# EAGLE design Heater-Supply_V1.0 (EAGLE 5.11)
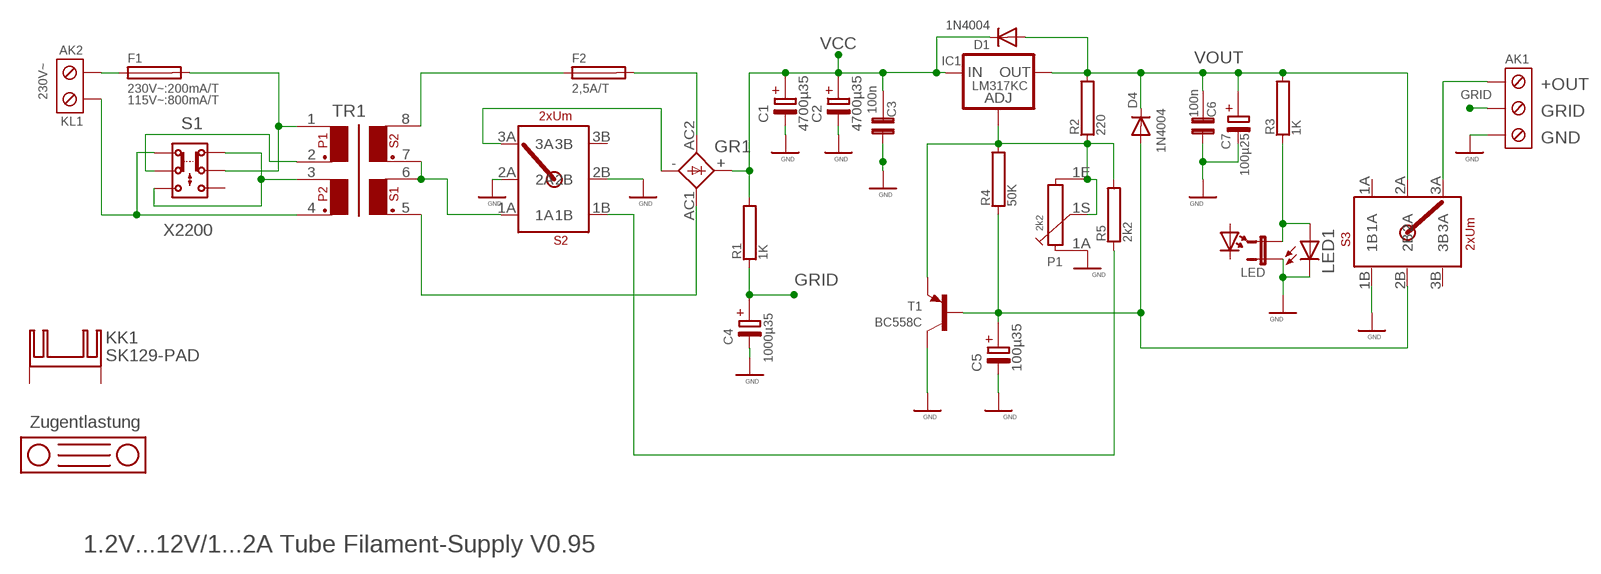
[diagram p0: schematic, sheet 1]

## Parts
AK1  KLEMME3STANDART  [KLEMME3]
AK2  KL1  KLEMME2RM5  [KLEMME2]
C1  4700µ35  E7,5-18  [E7,5-18]
C2  4700µ35  E7,5-18  [E7,5-18]
C3  100n  C2,5/55/2  [C2,5/5-2]
C4  1000µ35  E5-13  [E5-13]
C5  100µ35  E3,5-8  [E3,5-8]
C6  100n  C2,5/55/2  [C2,5/5-2]
C7  100µ25  E2,5-7  [E2,5-7]
D1  1N4004  [DO41-10]
D4  1N4004  [DO41-10]
F1  230V~:200mA/T  SH22,5A  [SH22,5A]
F2  2,5A/T  SH22,5A  [SH22,5A]
GR1  FBU4  [FBU4]
IC1  LM317KC  LM317TS  [317TS]
KK1  SK129-PAD  [SK129]
LED  JP1E  [JP1]
LED1  LED3MM  [LED3MM]
P1  2k2  PC16-SHM2  [PC16-SHM2]
R1  1K  0207/10RD  [0207/10]
R2  220  0207/10RD  [0207/10]
R3  1K  0207/10RD  [0207/10]
R4  50K  0207/10RD  [0207/10]
R5  2k2  0207/10RD  [0207/10]
S1  X2200  [X2200]
S2  2xUm  S-2PRINT  [S-2PRINT]
S3  2xUm  S-2PRINT  [S-2PRINT]
T1  BC558C  BC558C-PNP-TO92-EBC  [TO92-EBC]
TR1  FL24/12  [FL12-24]
U$2  KAZU0442  [KAZU0442]

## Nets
GND: AK1.1 C1.- C2.- C3.2 C3.3 C4.- C5.- C6.2 C6.3 C7.- LED1.K(C) LED.1 P1.1A S2.2A S2.2B S3.1B T1.C
GRID: AK1.2 C4.+ R1.1
N$1: F2.1 TR1.8
N$2: AK1.3 S3.3A
N$3: S2.1A TR1.6 TR1.7
N$4: AK2.1 F1.1
N$5: F1.2 S1.1.2 TR1.1
N$6: S1.2.2 TR1.2
N$7: GR1.- S2.3A
N$9: C5.+ D4.A R4.1 S3.2B T1.B
N$10: R5.1 S2.1B
N$13: LED1.A LED.2 R3.1
N$15: IC1.1(ADJ) P1.1E P1.1S R2.1 R4.2 R5.2 T1.E
N$18: AK2.2 S1.2.1 TR1.4
N$20: GR1.AC1(AC2) TR1.5
N$21: F2.2 GR1.AC2(AC1)
N$24: S1.1.1 S1.2.3 TR1.3
VCC: C1.+ C2.+ C3.1 D1.C GR1.+ IC1.3(IN) R1.2
VOUT: C6.1 C7.+ D1.A D4.C IC1.2(OUT) R2.2 R3.2 S3.2A
Unconnected: KK1.A2,5(K) KK1.B2,5(K) P1.M1 P1.M2 P1.M3 P1.M4 S1.1.3 S2.3B S3.1A S3.3B

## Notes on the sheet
- +OUT
- 230V~
- 115V~:800mA/T
- GRID
- GND
- Zugentlastung
- 1.2V...12V/1...2A Tube Filament-Supply V0.95

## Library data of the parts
AK1 = VERBINDE:KLEMME3
AK2 = VERBINDE:KLEMME2
C1 C2 = Elkos:E7,5-18
C3 C6 = CAP-Kondensatoren:C2,5/5
C4 = Elkos:E5-13
C5 = Elkos:E3,5-8
C7 = Elkos:E2,5-7
D1 D4 = diode:1N4004: DIODE
F1 F2 = fuse:SH22,5A: FUSE HOLDER; MPN: 0031.7701.11; OC_FARNELL: unknown; OC_NEWARK: 04F1224
GR1 = Gleichrichter:FBU4: FAGOR RECTIFIER grid 3 x 5 mm
IC1 = v-reg:LM317TS: VOLTAGE REGULATOR
KK1 = heatsink:SK129-PAD: HEATSINK
LED = jumper:JP1E: JUMPER
LED1 = led:LED: LED
P1 = Potentiometer-piher:PC16-SHM2: POTENTIOMETER single carbon potentiometer, 16 mm, S3ROH
R1-R5 = R:0207/10
S1 = switch:X2200
S2 S3 = Schalter:S-2PRINT
T1 = transistor:*-PNP-: PNP Transistror
TR1 = trafo:FL24/12
U$2 = MB:KAZU0442

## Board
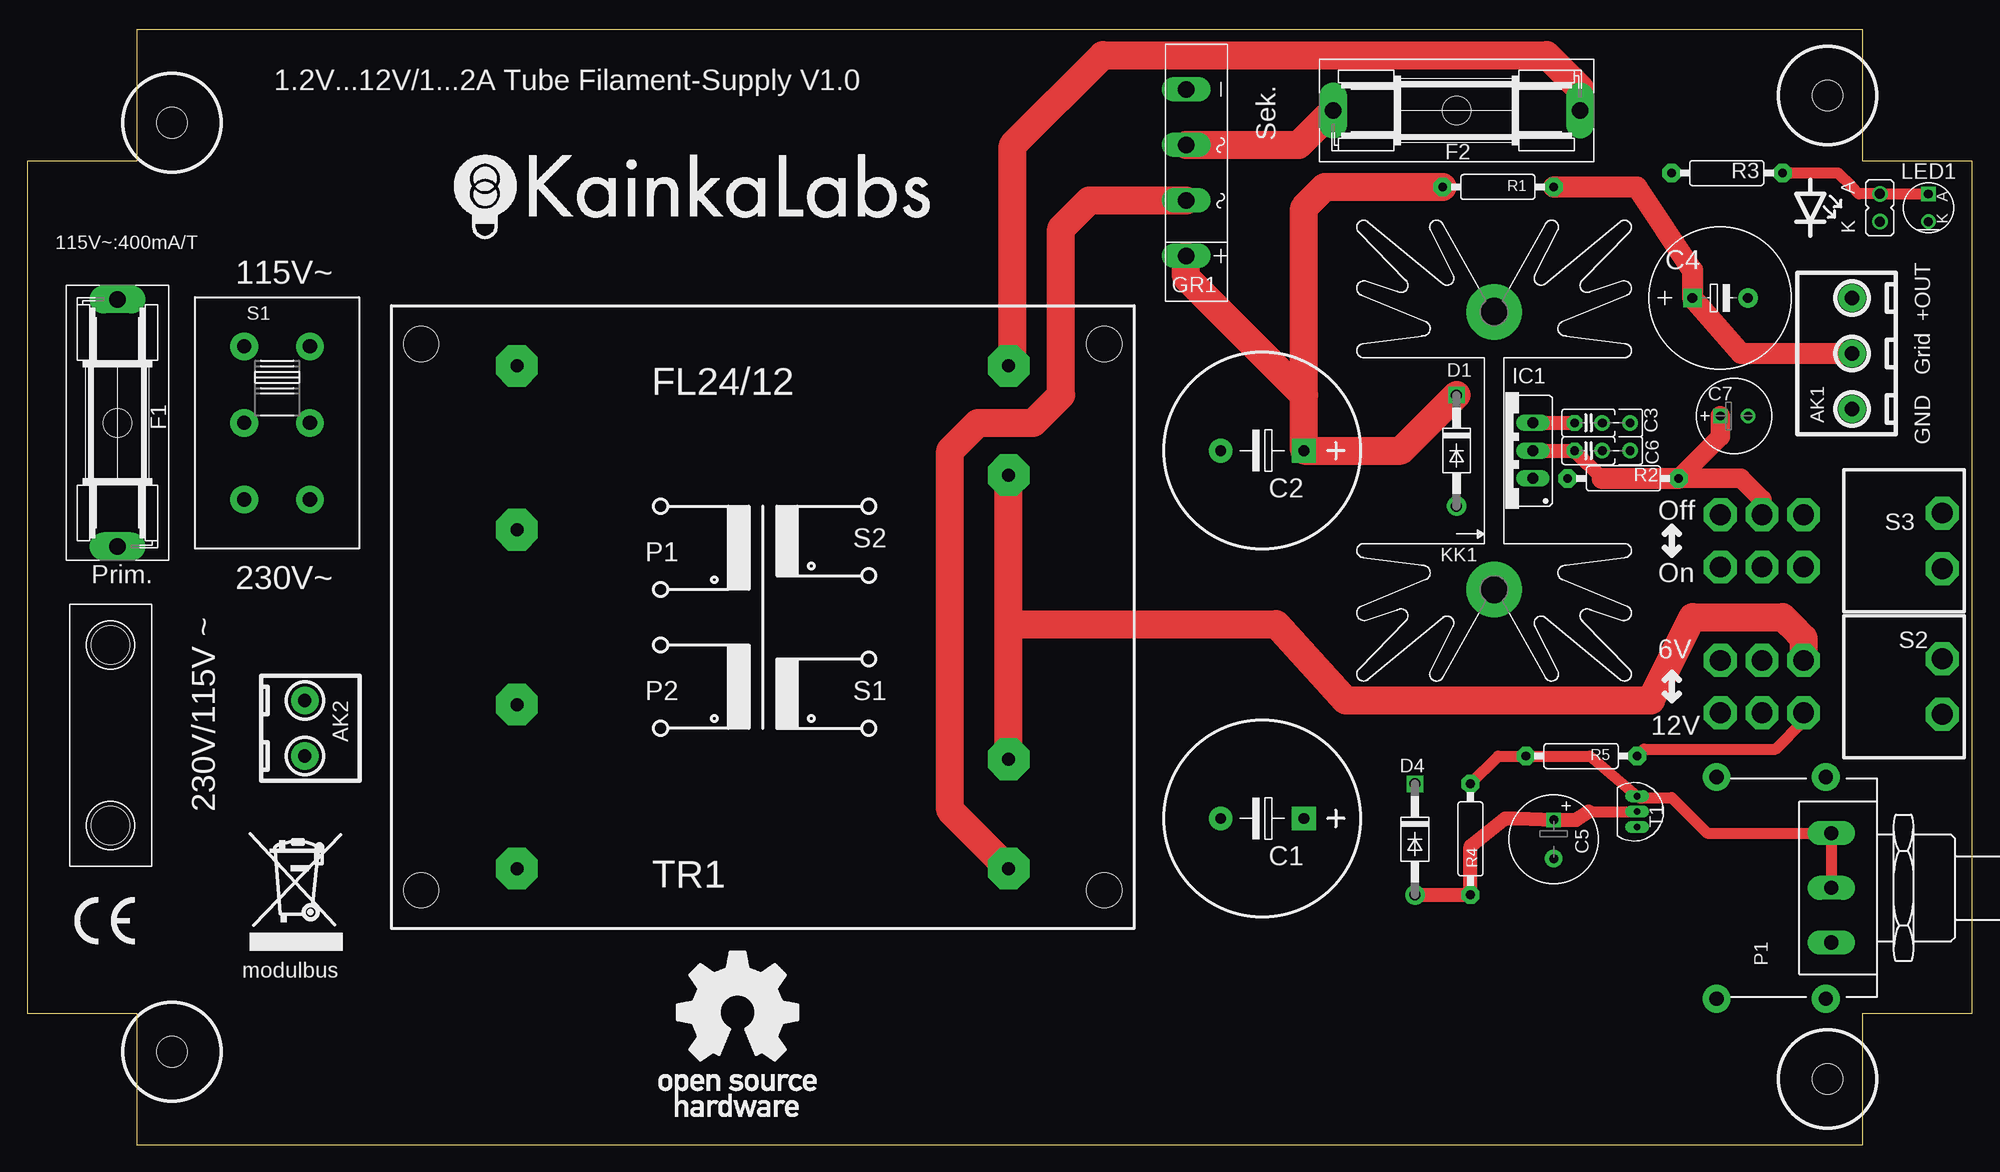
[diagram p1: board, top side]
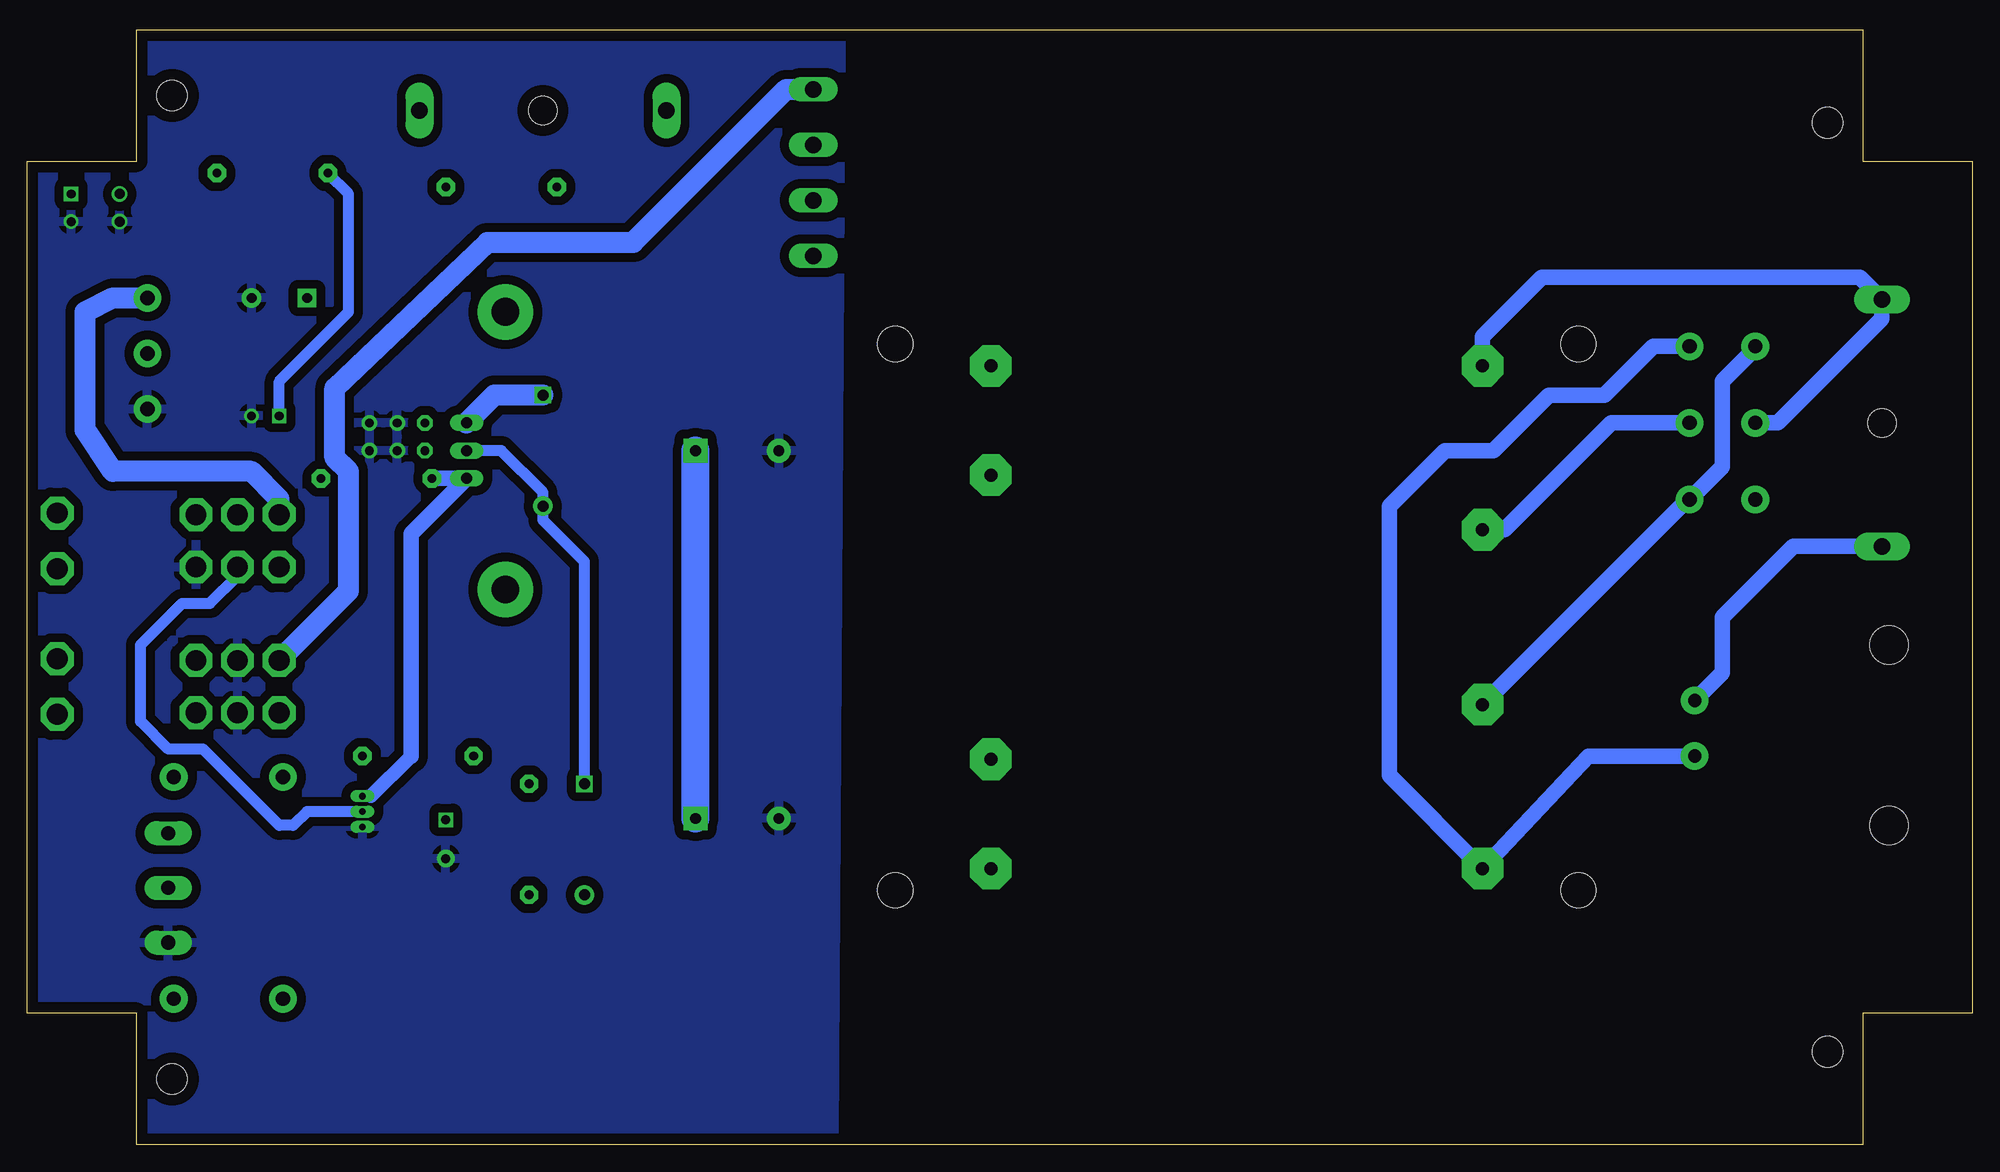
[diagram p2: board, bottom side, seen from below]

Size 178 x 102 mm. Coordinates in mm from the lower left corner, seen from the top.
Copper layers (1*16): Top 0.035mm / dielectric 1.5mm / Bottom 0.035mm
Design rules "default": minimum track width 10mil, minimum drill 23mil, track to track 8mil, track to pad 8mil, pad to pad 8mil, via to via 8mil, smd to smd 8mil, copper to edge 40mil, drill to drill 8mil, minimum pad ring 10mil, minimum via ring 8mil, stop-mask expansion 4mil, vias tented up to drill 0mil, thermal gap 20mil

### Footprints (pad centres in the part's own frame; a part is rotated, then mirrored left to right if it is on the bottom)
KLEMME3 = drill 1.3 pad 2.54 round: 1 0,0; 2 5.08,0; 3 10.16,0
KLEMME2 = drill 1.2 pad 2.54 round: 1 0,0; 2 5.08,0
E7,5-18 = drill 1 pad 2.184 square: + -3.81,0 | drill 1 pad 2.184 round: - 3.81,0
C2,5/5-2 = drill 0.8 pad 1.422 octagon: 1 -2.54,0 | drill 0.8 pad 1.422 round: 2 0,0; 3 2.54,0
E5-13 = drill 0.9 pad 1.676 square: + -2.54,0 | drill 0.9 pad 1.778 round: - 2.54,0
E3,5-8 = drill 0.813 square: + -1.778,0 | drill 0.813 pad 1.6 round: - 1.778,0
E2,5-7 = drill 0.8 square: + -1.27,0 | drill 0.8 round: - 1.27,0
DO41-10 = drill 1 pad 1.778 round: A 5.08,0 | drill 1 square: C -5.08,0
SH22,5A = drill 1.5 pad 2.54 long: 1 -11.3,0; 2 11.3,0 | hole 2.6: 0,0
BO-E450 = hole 2.8: 13.25,8.5; 164.75,6; 13.25,93.5; 164.75,96
FBU4 = drill 1.499 long: + 7.62,-1.54; - -7.62,-1.54; AC1 2.54,-1.54; AC2 -2.54,-1.54
317TS = drill 1.016 long: 1 -2.54,-2.54; 2 0,-2.54; 3 2.54,-2.54
SK129 = drill 2.54 pad 5.08 round: A2,5 -12.7,-0.889; B2,5 12.7,-0.889
JP1 = drill 0.914 round: 1 0,-1.27; 2 0,1.27
LED3MM = drill 0.8 square: A -1.27,0 | drill 0.8 round: K 1.27,0
PC16-SHM2 = drill 1.3 pad 2.184 long: 1A -5,0; 1E 5,0; 1S 0,0 | drill 1.3 pad 2.54 round: M1 -10.15,0.5; M2 10.15,0.5; M3 10.15,10.5; M4 -10.15,10.5
0207/10 = drill 0.8 pad 1.676 octagon: 1 -5.08,0; 2 5.08,0
X2200 = drill 1.3 pad 2.54 round: 1.1 -7,-3; 1.2 0,-3; 1.3 7,-3; 2.1 -7,3; 2.2 0,3; 2.3 7,3
S-2PRINT = drill 1.9 pad 3 octagon: 1A 12.7,-2.4; 1B 12.7,2.4; 2A 16.5,-2.4; 2B 16.5,2.4; 3A 20.3,-2.4; 3B 20.3,2.4; P$1 0,2.54; P$2 0,-2.54
TO92-EBC = drill 0.6 long: B 0,0; C 1.4,0; E -1.4,0
FL12-24 = drill 1.194 pad 3.81 octagon: 1 -22.5,23; 2 -22.5,8; 3 -22.5,-8; 4 -22.5,-23; 5 22.5,-23; 6 22.5,-13; 7 22.5,13; 8 22.5,23 | hole 3.2: -31.25,-25; -31.25,25; 31.25,25; 31.25,-25
KAZU0442 = hole 3.5: 0,0; 16.5,0

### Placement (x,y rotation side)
AK1  167,67.31 90 top
AK2  25.4,40.64 270 top
C1  113.03,29.84 180 top
C2  113.03,63.5 180 top
C3  144.15,66.04 0 top
C4  154.94,77.47 0 top
C5  139.7,27.94 270 top
C6  144.15,63.5 0 top
C7  156.21,66.67 0 top
D1  130.81,63.5 270 top
D4  127,27.94 270 top
F1  8.26,66.04 90 top
F2  130.81,94.61 180 top
GEHÄUSE  [BO-E450]  0,0 0 top
GR1  107.59,88.94 270 top
IC1  135.25,63.5 90 top
KK1  133.35,63.5 90 top
LED  169.54,85.72 0 top
LED1  173.99,85.72 270 top
P1  165.1,23.5 90 top
R1  134.62,87.63 180 top
R2  146.05,60.96 0 top
R3  155.57,88.9 180 top
R4  132.08,27.94 90 top
R5  142.24,35.56 180 top
S1  22.86,66.04 270 top
S2  175.26,41.91 180 top
S3  175.26,55.24 180 top
T1  147.32,30.48 270 top
TR1  67.31,48.26 0 top
U$2  7.62,29.21 90 top
U$3  [KAINKALABS40MM]  39.04,82.88 0 top
U$4  [OSH15MM]  57.78,2.54 0 top
U$5  [EAR]  20.36,17.78 0 top
U$7  [LED]  163.19,88.27 270 top
U$8  [CE6MM]  4.33,18.34 0 top

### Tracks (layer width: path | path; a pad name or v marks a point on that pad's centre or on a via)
GND
  pour Bottom (isolate 0.813): 103.53,101.39 104.16,0.38 168.1,0 167.47,12.19 177.93,12.19 177.93,90.17 168.1,90.17 168.1,102.02
GRID
  Top 1.93: AK1.2 158.12,72.39 156.84,72.39 C4.+ 152.4,80.01 147.32,87.63 R1.1
N$1
  Top 1.27: TR1.8 90.17,71.62
  Top 2.54: F2.1 142.11,96.65 139.06,99.69 98.42,99.69 90.17,91.44 90.17,71.62
N$2
  Bottom 1.93: S3.3A 154.96,59.08 157.48,61.59 170.18,61.59 172.72,65.41 172.72,76.2 170.18,77.47 AK1.3
N$3
  Top 2.54: TR1.6 89.81,47.62 | 89.81,47.62 TR1.7 | S2.1A 162.56,46.35 161.29,47.62 160.66,48.26 152.4,48.26 148.59,40.64 120.65,40.64 114.3,47.62 89.81,47.62
N$4
  Bottom 1.422: F1.1 16.38,54.74 22.86,48.26 22.86,43.18 AK2.1
N$5
  Bottom 1.422: S1.1.2 17.78,66.04 8.26,75.56 F1.2 10.29,79.38 39.37,79.38 44.81,73.94 TR1.1
N$6
  Bottom 1.422: TR1.2 42.8,56.26 33.02,66.04 S1.2.2
N$7
  Bottom 1.93: GR1.- 108.55,96.56 122.56,82.55 135.89,82.55 149.86,69.22 149.86,62.87 148.59,61.59 148.59,50.68 S2.3A
N$9
  Top 1.016: 142.88,30.48 T1.B
  Top 1.27: D4.A R4.1 132.08,27.3 135.25,29.84 136.4,29.84 C5.+ 141.73,29.72 142.88,30.48
  Bottom 1.016: T1.B 152.4,30.48 153.67,29.21 154.94,29.21 160.66,34.92 161.93,36.2 165.1,36.2 167.64,38.73 167.64,45.72 163.83,49.53 161.29,49.53 158.75,52.07 S3.2B
N$10
  Top 1.016: R5.1 147.96,36.2 160.02,36.2 162.56,38.73 S2.1B
N$13
  Top 1.016: R3.1 165.74,88.9 167,87.63 167.64,87 LED.2 LED1.A
N$15
  Top 1.016: P1.1S P1.1E 153.75,28.5 150.5,31.75 147.45,31.75 T1.E 143,35.56 R5.2 134.62,35.56 R4.2
  Bottom 1.016: T1.E 146.56,31.88
  Bottom 1.27: 146.56,31.88 142.88,35.56
  Bottom 1.422: R2.1 IC1.1 142.88,55.88 142.88,35.56
N$18
  Bottom 1.422: AK2.2 35.15,35.56 TR1.4 53.34,33.79 53.34,58.42 48.26,63.5 43.81,63.5 38.73,68.58 33.66,68.58 31.75,70.48 29.2,73.04 S1.2.1
N$20
  Top 2.54: GR1.AC1 97.19,86.39 94.61,83.82 94.61,68.58 92.08,66.04 87,66.04 84.45,63.5 84.45,30.61 TR1.5
N$21
  Top 2.54: GR1.AC2 116.37,91.47 F2.2
N$24
  Bottom 0.813: 19.86,72.85 S1.1.1 | 26.03,59.04 S1.2.3
  Bottom 1.422: 19.86,72.85 22.86,69.85 22.86,62.04 S1.2.3 | TR1.3 26.03,59.04
VCC
  Top 1.27: IC1.3 C3.1
  Top 2.54: GR1.+ 106.05,79.37 116.84,68.58 C2.+ | C2.+ 125.73,63.5 D1.C | R1.2 123.83,87.63 118.75,87.63 116.84,85.72 C2.+
  Bottom 1.93: D1.C 135.25,68.58 IC1.3
  Bottom 2.54: C1.+ C2.+
VOUT
  Top 1.016: 158.75,57.66 S3.2A
  Top 1.27: IC1.2 C6.1 144.15,60.96
  Top 1.778: 158.75,57.66 158.75,59.05 156.84,60.96 R2.2 154.94,64.77 C7.+
  Top 1.93: 144.15,60.96 R2.2
  Bottom 1.016: IC1.2 134.62,63.5 130.81,59.69 D1.A 130.81,57.15 127,53.34 D4.C | R3.2 148.59,87 148.59,76.2 154.94,69.85 C7.+

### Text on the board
tPlace: Sek. | 1.2V...12V/1...2A Tube Filament-Supply V1.0 | A | K | 115V~:400mA/T | +OUT | 115V~ | Grid | GND | Off | Prim. | 230V~ | On | 6V | 12V | 230V/115V ~ | modulbus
